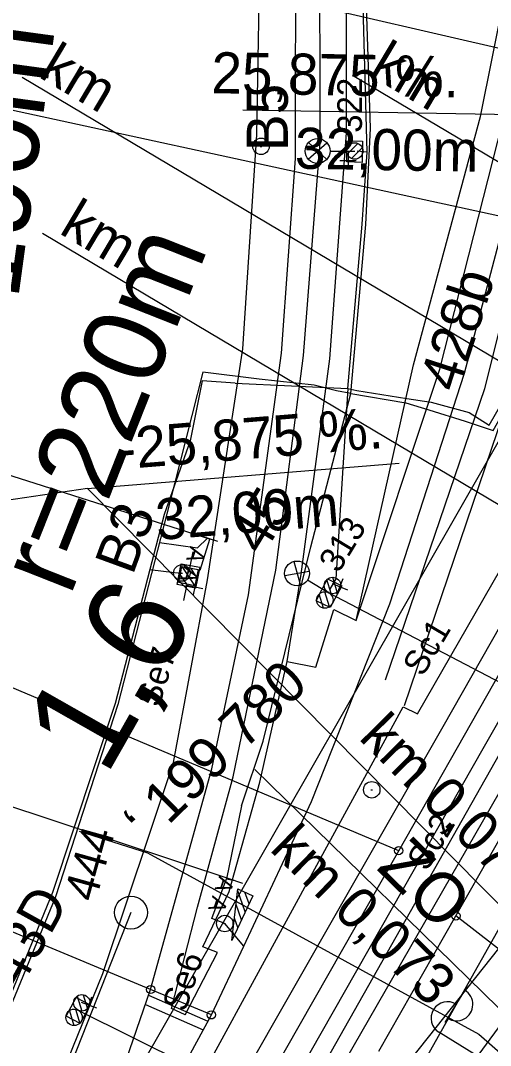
# Model space of a CAD drawing. Extents: x -598638 to -597933, y -1164002 to -1161904.
# Drawn here: x -598153.6 to -598125.1, y -1162835.6 to -1162773.3 of the extents above; entities that cross this region are included whole.
import ezdxf

# ---------------------------------------------------------------- set-up
doc = ezdxf.new("R2010")
doc.units = 0
for name, color, linetype in [('Vrstva 1', 7, 'Continuous'), ('Vrstva 11', 7, 'Continuous'), ('Vrstva 12', 7, 'Continuous'), ('Vrstva 25', 7, 'Continuous'), ('Vrstva 26', 7, 'Continuous'), ('Vrstva 28', 7, 'Continuous'), ('Vrstva 3', 7, 'Continuous'), ('Vrstva 4', 7, 'Continuous'), ('Vrstva 43', 7, 'Continuous'), ('Vrstva 44', 7, 'Continuous'), ('Vrstva 51', 7, 'Continuous'), ('Vrstva 6', 7, 'Continuous'), ('Vrstva 63', 7, 'Continuous'), ('Vrstva 7', 7, 'Continuous')]:
    doc.layers.add(name, color=color, linetype=linetype)

msp = doc.modelspace()

# ---------------------------------------------------------------- linework, layer by layer
at = {"layer": 'Vrstva 1'}
for p, q in [((-598179.707, -1162762.202), (-598122.033, -1162775.573)), ((-598121.14, -1162779.08), (-598140.138, -1162778.753)), ((-598130.653, -1162823.786), (-598208.738, -1162790.839)), ((-598149.562, -1162801.766), (-598130.625, -1162800.222)), ((-598149.562, -1162801.766), (-598168.362, -1162804.518)), ((-598116.195, -1162835.531), (-598149.562, -1162801.766)), ((-598139.409, -1162818.844), (-598119.244, -1162838.594)), ((-598069.482, -1162872.78), (-598127.174, -1162827.753))]:
    msp.add_line(p, q, dxfattribs=at)
for points in [[(-598185.535, -1162920.228), (-598173.482, -1162899.031), (-598147.832, -1162853.978), (-598130.653, -1162823.786), (-598124.876, -1162813.622), (-598094.683, -1162760.579), (-598072.513, -1162721.65)], [(-598148.903, -1162841.412), (-598145.736, -1162832.228), (-598142.003, -1162818.806), (-598139.787, -1162808.236), (-598137.783, -1162793.528), (-598136.933, -1162781.691), (-598136.909, -1162767.649), (-598137.878, -1162754.511), (-598139.595, -1162742.333), (-598141.999, -1162730.629), (-598144.153, -1162722.384)], [(-598131.857, -1162835.983), (-598127.174, -1162827.753), (-598120.322, -1162815.699), (-598090.855, -1162763.955), (-598078.437, -1162742.118)], [(-598124.171, -1162785.282), (-598204.376, -1162767.837), (-598201.647, -1162755.291), (-598220.808, -1162751.123)], [(-598146.747, -1162842.466), (-598142.041, -1162833.77), (-598140.075, -1162829.587), (-598135.947, -1162820.802), (-598131.192, -1162808.778), (-598126.663, -1162794.757), (-598124.171, -1162785.282), (-598123.05, -1162780.413), (-598122.033, -1162775.573)], [(-598142.041, -1162833.77), (-598145.736, -1162832.228), (-598280.672, -1162775.962)], [(-598148.348, -1162864.87), (-598137.826, -1162846.438), (-598130.316, -1162836.985), (-598124.577, -1162829.729), (-598115.364, -1162818.081), (-598094.508, -1162796.091)]]:
    msp.add_lwpolyline(points, dxfattribs=at)
for centre in [(-598130.653, -1162823.786), (-598127.174, -1162827.753), (-598145.735, -1162832.228), (-598142.041, -1162833.771)]:
    msp.add_circle(centre, 0.25, dxfattribs=at)
at = {"layer": 'Vrstva 11'}
for p, q in [((-598133.791, -1162781.424), (-598133.145, -1162780.778)), ((-598133.531, -1162781.694), (-598132.876, -1162781.039)), ((-598143.344, -1162806.609), (-598143.15, -1162805.618)), ((-598143.041, -1162807.654), (-598143.81, -1162806.507)), ((-598142.939, -1162807.134), (-598143.29, -1162806.61)), ((-598143.542, -1162807.579), (-598143.932, -1162806.999)), ((-598134.754, -1162808.15), (-598135.015, -1162807.294)), ((-598134.388, -1162808.065), (-598134.663, -1162807.16)), ((-598143.535, -1162807.577), (-598143.73, -1162808.562)), ((-598134.862, -1162808.949), (-598135.138, -1162808.042)), ((-598135.229, -1162809.033), (-598135.488, -1162808.179)), ((-598150.197, -1162832.63), (-598149.923, -1162833.538)), ((-598149.83, -1162832.548), (-598149.572, -1162833.402)), ((-598150.672, -1162833.515), (-598150.397, -1162834.419)), ((-598150.306, -1162833.43), (-598150.046, -1162834.286))]:
    msp.add_line(p, q, dxfattribs=at)
msp.add_lwpolyline([(-598144.027, -1162807.484), (-598143.834, -1162806.503), (-598142.853, -1162806.696), (-598143.046, -1162807.677)], close=True, dxfattribs=at)
for points in [[(-598144.027, -1162807.484), (-598143.834, -1162806.503), (-598142.853, -1162806.696), (-598143.046, -1162807.677), (-598144.027, -1162807.484)], [(-598134.91, -1162808.1), (-598112.16, -1162820)], [(-598150.15, -1162833.48), (-598130.19, -1162843.41)]]:
    msp.add_lwpolyline(points, dxfattribs=at)
for centre in [(-598133.33, -1162781.24), (-598134.675, -1162807.659), (-598134.675, -1162807.659), (-598135.145, -1162808.541), (-598135.145, -1162808.541), (-598149.914, -1162833.039), (-598149.914, -1162833.039), (-598150.386, -1162833.921), (-598150.386, -1162833.921)]:
    msp.add_circle(centre, 0.5, dxfattribs=at)
at = {"layer": 'Vrstva 12'}
for p, q in [((-598144.12, -1162807.6), (-598143.87, -1162806.34)), ((-598143.87, -1162806.34), (-598142.75, -1162806.55)), ((-598142.75, -1162806.55), (-598143, -1162807.82)), ((-598143, -1162807.82), (-598144.12, -1162807.6))]:
    msp.add_line(p, q, dxfattribs=at)
for points in [[(-598133.81, -1162781.9), (-598133.8, -1162780.62), (-598132.85, -1162780.63), (-598132.88, -1162781.94), (-598133.81, -1162781.9)], [(-598134.11, -1162807.67), (-598134.82, -1162809), (-598135.68, -1162808.6), (-598134.99, -1162807.25), (-598134.11, -1162807.67)], [(-598149.41, -1162833.16), (-598150.02, -1162834.3), (-598150.86, -1162833.84), (-598150.26, -1162832.71), (-598149.41, -1162833.16)]]:
    msp.add_lwpolyline(points, dxfattribs=at)
at = {"layer": 'Vrstva 25'}
for p, q in [((-598136.149, -1162781.736), (-598135.023, -1162780.734)), ((-598136.133, -1162780.721), (-598135.025, -1162781.744)), ((-598134.83, -1162781.24), (-598133.33, -1162781.24)), ((-598137.037, -1162806.202), (-598136.62, -1162807.651)), ((-598143.887, -1162806.902), (-598143.787, -1162806.902)), ((-598137.577, -1162807.061), (-598136.095, -1162806.789)), ((-598136.192, -1162807.322), (-598134.91, -1162808.1)), ((-598141.277, -1162828.216), (-598141.177, -1162828.216)), ((-598127.84, -1162834.231), (-598126.476, -1162832.017)), ((-598125.228, -1162836.663), (-598128.207, -1162834.827))]:
    msp.add_line(p, q, dxfattribs=at)
for centre, radius in [((-598135.584, -1162781.238), 0.754), ((-598136.833, -1162806.925), 0.754), ((-598143.837, -1162806.902), 0.5), ((-598141.227, -1162828.216), 0.5)]:
    msp.add_circle(centre, radius, dxfattribs=at)
for centre, start, end in [((-598127.148, -1162833.13), 237.65743, 59.06258), ((-598127.683, -1162833.975), 58.36001, 238.36001)]:
    msp.add_arc(centre, 1, start, end, dxfattribs=at)
at = {"layer": 'Vrstva 26'}
for points in [[(-598133.739, -1162795.688), (-598132.883, -1162785.694), (-598132.561, -1162781.304), (-598132.833, -1162771.673), (-598133.507, -1162753.613), (-598135.242, -1162744.453), (-598136.578, -1162735.815), (-598138.623, -1162726.488)], [(-598132.561, -1162781.304), (-598133.184, -1162781.255)], [(-598133.194, -1162795.797), (-598130.15, -1162796.289), (-598128.676, -1162796.517), (-598126.372, -1162797.148), (-598125.165, -1162797.901), (-598118.291, -1162785.968)], [(-598140.604, -1162795.346), (-598142.6, -1162795.212), (-598143.324, -1162798.859)], [(-598140.604, -1162795.346), (-598133.739, -1162795.688), (-598133.194, -1162795.797)], [(-598133.739, -1162795.688), (-598134.467, -1162807.255)], [(-598143.324, -1162798.859), (-598144.902, -1162803.35)], [(-598144.902, -1162803.35), (-598145.773, -1162806.692), (-598147.895, -1162814.835), (-598151.697, -1162826.333), (-598155.502, -1162835.602), (-598159.885, -1162844.8), (-598162.416, -1162850.038), (-598164.36, -1162853.511), (-598166.042, -1162857.118), (-598164.26, -1162864.862)], [(-598145.773, -1162806.692), (-598144.273, -1162806.868), (-598143.837, -1162806.902)], [(-598134.467, -1162807.255), (-598134.839, -1162807.891)], [(-598150.081, -1162822.602), (-598145.925, -1162823.915), (-598125.776, -1162834.952), (-598123.525, -1162836.909), (-598124.091, -1162837.542), (-598129.205, -1162843.998)]]:
    msp.add_lwpolyline(points, dxfattribs=at)
at = {"layer": 'Vrstva 28'}
msp.add_line((-598140.207, -1162821.051), (-598141.115, -1162825.493), dxfattribs=at)
for points in [[(-598133.568, -1162795.979), (-598132.654, -1162785.702), (-598132.374, -1162779.841), (-598132.629, -1162771.78), (-598133.203, -1162756.346), (-598133.291, -1162753.897), (-598135.063, -1162744.423), (-598136.348, -1162735.985), (-598138.696, -1162725.492), (-598140.441, -1162720.483), (-598146.202, -1162709.244), (-598149.531, -1162710.126), (-598150.562, -1162710.327), (-598151.192, -1162706.084), (-598153.437, -1162698.629), (-598154.996, -1162692.989), (-598155.846, -1162690.77), (-598154.797, -1162690.331), (-598151.984, -1162689.455), (-598149.559, -1162688.581), (-598149.218, -1162687.385), (-598151.36, -1162675.56), (-598154.253, -1162659.137), (-598152.294, -1162657.885)], [(-598133.568, -1162795.979), (-598130.221, -1162796.559), (-598128.822, -1162796.97), (-598126.618, -1162797.673), (-598124.922, -1162798.23), (-598117.755, -1162785.562)], [(-598140.207, -1162821.051), (-598138.9, -1162817.123), (-598135.993, -1162805.307), (-598133.568, -1162795.979), (-598134.442, -1162795.825), (-598135.794, -1162795.467), (-598139.137, -1162795.121), (-598142.554, -1162794.689), (-598144.563, -1162802.596), (-598147.734, -1162814.888), (-598151.511, -1162826.59), (-598155.288, -1162835.731), (-598159.67, -1162844.896), (-598162.194, -1162850.186), (-598164.133, -1162853.664), (-598165.736, -1162857.055), (-598164.017, -1162864.873)], [(-598145.197, -1162805.054), (-598142.887, -1162805.379), (-598142.27, -1162804.791)], [(-598140.075, -1162829.587), (-598141.227, -1162828.216), (-598142.007, -1162827.909), (-598141.115, -1162825.493)], [(-598141.115, -1162825.493), (-598140.617, -1162825.598)]]:
    msp.add_lwpolyline(points, dxfattribs=at)
at = {"layer": 'Vrstva 3'}
for p, q in [((-598139.979, -1162827.501), (-598140.441, -1162826.218)), ((-598139.753, -1162827.021), (-598140.012, -1162826.301)), ((-598139.528, -1162826.542), (-598139.533, -1162826.527)), ((-598140.204, -1162827.981), (-598140.54, -1162827.052)), ((-598140.43, -1162828.461), (-598140.638, -1162827.884)), ((-598140.656, -1162828.942), (-598140.736, -1162828.716))]:
    msp.add_line(p, q, dxfattribs=at)
msp.add_lwpolyline([(-598140.799, -1162829.247), (-598140.429, -1162826.107), (-598139.524, -1162826.531), (-598140.799, -1162829.247)], dxfattribs=at)
msp.add_lwpolyline([(-598140.799, -1162829.247), (-598140.429, -1162826.107), (-598139.524, -1162826.531), (-598140.799, -1162829.247)], dxfattribs=at)
at = {"layer": 'Vrstva 4'}
for points in [[(-598189.853, -1162912.957), (-598181.357, -1162896.669), (-598172.758, -1162881.845), (-598166.709, -1162871.526), (-598158.957, -1162856.49), (-598153.453, -1162843.163), (-598148.638, -1162831.263), (-598144.347, -1162818.421), (-598142.283, -1162807.307), (-598140.136, -1162793.268), (-598139.285, -1162780.248), (-598139.053, -1162767.58), (-598140.211, -1162754.845), (-598141.396, -1162743.83), (-598143.05, -1162731.285)], [(-598136.668, -1162850.995), (-598119.65, -1162827.832), (-598111.306, -1162818.425), (-598097.627, -1162804.2), (-598093.831, -1162800.263), (-598081.499, -1162787.848), (-598070.515, -1162776.315), (-598054.627, -1162758.515)], [(-598137.443, -1162812.291), (-598135.696, -1162812.632), (-598134.599, -1162809.128)]]:
    msp.add_lwpolyline(points, dxfattribs=at)
at = {"layer": 'Vrstva 43'}
msp.add_circle((-598146.929, -1162827.551), 1, dxfattribs=at)
at = {"layer": 'Vrstva 44'}
for points in [[(-598295.758, -1163493.483), (-598278.118, -1163452.874), (-598264.209, -1163410.565), (-598254.468, -1163367.19), (-598248.62, -1163321.577), (-598253.497, -1163320.887), (-598249.615, -1163272.581), (-598247.635, -1163222.481), (-598247.486, -1163176.779), (-598247.442, -1163130.148), (-598244.014, -1163084.171), (-598235.33, -1163037.762), (-598224.817, -1163002.559), (-598219.379, -1163002.169), (-598206.652, -1162968.487), (-598191.401, -1162936.053), (-598173.754, -1162904.506), (-598155.689, -1162873.083), (-598136.14, -1162838.446), (-598116.776, -1162804.197)], [(-598214.433, -1163003.397), (-598199.219, -1162964.022), (-598185.65, -1162936.04), (-598163.291, -1162895.981), (-598150.219, -1162876.092), (-598140.441, -1162856.726), (-598110.998, -1162804.439)], [(-598146.929, -1162827.551), (-598158.836, -1162857.646), (-598178.917, -1162893.572)]]:
    msp.add_lwpolyline(points, dxfattribs=at)
at = {"layer": 'Vrstva 51'}
for points in [[(-598178.434, -1162902.74), (-598173.075, -1162891.876), (-598150.908, -1162852.698), (-598130.373, -1162815.033), (-598129.52, -1162815.457), (-598097.649, -1162759.965), (-598075.416, -1162720.73), (-598062.421, -1162699.093), (-598047.075, -1162676.157), (-598029.931, -1162650.253)], [(-598178.434, -1162902.74), (-598177.624, -1162903.197), (-598171.581, -1162892.624), (-598149.282, -1162853.595), (-598127.952, -1162816.235), (-598096.388, -1162760.674), (-598074.046, -1162721.426), (-598061.02, -1162699.878), (-598045.71, -1162676.963), (-598028.725, -1162651.098), (-598029.931, -1162650.253)], [(-598243.76, -1163139.382), (-598243.393, -1163128.836), (-598242.662, -1163113.52), (-598241.121, -1163096.732), (-598238.542, -1163077.297), (-598236.364, -1163063.881), (-598233.006, -1163047.35), (-598229.452, -1163032.186), (-598222.566, -1163008.635), (-598216.788, -1162991.447), (-598211.314, -1162977.141), (-598198.954, -1162949.031), (-598191.954, -1162935.136), (-598181.215, -1162915.654), (-598172.367, -1162900.092), (-598146.639, -1162854.694), (-598125.435, -1162817.431), (-598123.403, -1162813.873), (-598093.874, -1162762.323), (-598071.494, -1162722.83), (-598058.726, -1162701.732), (-598043.403, -1162678.606), (-598026.165, -1162652.845)], [(-598239.095, -1163097.092), (-598236.576, -1163077.501), (-598234.309, -1163064.254), (-598231.064, -1163047.867), (-598227.331, -1163032.522), (-598220.677, -1163009.309), (-598214.847, -1162992.197), (-598209.449, -1162977.846), (-598197.189, -1162949.981), (-598190.09, -1162935.876), (-598179.544, -1162916.618), (-598170.666, -1162900.915), (-598144.793, -1162855.5), (-598123.538, -1162818.503), (-598121.573, -1162814.996), (-598092.208, -1162763.361), (-598069.503, -1162724.253), (-598055.71, -1162703.114), (-598040.468, -1162680.627), (-598023.352, -1162655.056), (-598026.165, -1162652.845)], [(-598143.639, -1162833.769), (-598144.474, -1162833.39), (-598142.887, -1162827.226), (-598140.722, -1162819.3), (-598138.124, -1162806.733), (-598136.451, -1162793.663), (-598135.418, -1162780.713), (-598135.449, -1162767.439), (-598136.413, -1162754.506), (-598138.125, -1162741.945), (-598140.581, -1162730.014)], [(-598143.639, -1162833.769), (-598141.66, -1162829.974), (-598142.55, -1162829.627), (-598140.952, -1162826.266), (-598139.089, -1162819.621), (-598137.443, -1162812.291), (-598136.577, -1162806.979), (-598134.84, -1162793.881), (-598133.819, -1162780.129), (-598133.832, -1162767.002), (-598134.817, -1162754.969), (-598136.682, -1162741.592), (-598139.151, -1162729.736), (-598140.581, -1162730.014)], [(-598131.459, -1162813.387), (-598125.418, -1162795.68), (-598121.535, -1162780.187), (-598118.021, -1162762.938), (-598116.444, -1162763.202)], [(-598130.3, -1162814.964), (-598123.885, -1162796.017), (-598119.967, -1162780.726), (-598116.444, -1162763.202)], [(-598134.599, -1162809.128), (-598133.246, -1162809.796), (-598129.747, -1162794.246), (-598125.683, -1162779.142), (-598123.45, -1162768.029), (-598121.981, -1162768.211)], [(-598133.246, -1162809.796), (-598128.158, -1162794.502), (-598124.333, -1162779.452), (-598121.981, -1162768.211)]]:
    msp.add_lwpolyline(points, dxfattribs=at)
at = {"layer": 'Vrstva 6'}
for p, q in [((-598119.176, -1162797.214), (-598153.55, -1162776.76)), ((-598099.098, -1162797.092), (-598133.472, -1162776.638)), ((-598117.928, -1162806.716), (-598152.302, -1162786.262)), ((-598142.127, -1162804.836), (-598180.238, -1162792.692)), ((-598142.729, -1162806.724), (-598142.127, -1162804.838)), ((-598141.651, -1162804.99), (-598142.603, -1162804.686)), ((-598178.588, -1162813.02), (-598140.617, -1162825.598)), ((-598141.092, -1162825.441), (-598140.142, -1162825.755))]:
    msp.add_line(p, q, dxfattribs=at)
at = {"layer": 'Vrstva 63'}
msp.add_line((-598215.837, -1162958.494), (-598115.28, -1162782.61), dxfattribs=at)
at = {"layer": 'Vrstva 7'}
for p, q in [((-598139.073, -1162780.956), (-598138.973, -1162780.956)), ((-598133.736, -1162781.313), (-598133.736, -1162782.313)), ((-598134.236, -1162781.813), (-598133.236, -1162781.813)), ((-598142.942, -1162807.248), (-598143.146, -1162808.226)), ((-598134.693, -1162807.537), (-598133.767, -1162807.915)), ((-598134.041, -1162807.263), (-598134.419, -1162808.189)), ((-598143.533, -1162807.635), (-598142.555, -1162807.839)), ((-598132.341, -1162820.084), (-598132.241, -1162820.084)), ((-598149.961, -1162833.005), (-598149.017, -1162833.337)), ((-598149.323, -1162832.699), (-598149.655, -1162833.643)), ((-598145.856, -1162832.576), (-598142.252, -1162834.16)), ((-598146.052, -1162833.146), (-598142.539, -1162834.69))]:
    msp.add_line(p, q, dxfattribs=at)
for centre in [(-598139.023, -1162780.956), (-598132.291, -1162820.084)]:
    msp.add_circle(centre, 0.5, dxfattribs=at)

# ---------------------------------------------------------------- texts
at = {"layer": 'Vrstva 1'}
for s, height, rotation, p in [('r=190m', 5, 82.24109, (-598154.628, -1162796.434)), ('25,875 %.', 2.5, 359.01583, (-598142.057, -1162777.72)), ('32,00m', 2.5, 359.01583, (-598136.976, -1162782.308)), ('r=220m', 5, 68.42323, (-598150.634, -1162808.384)), ('428b', 2.5, 72.09874, (-598127.063, -1162795.995)), ('-25,875 %.', 2.5, 4.66008, (-598147.65, -1162800.606)), ('32,00m', 2.5, 4.66008, (-598145.326, -1162804.905)), ('‘ 199 780  ', 2.5, 44.66008, (-598145.846, -1162823.448)), ('km 0,077', 2.5, 314.66008, (-598133.137, -1162816.964)), ('km 0,073', 2.5, 315.62032, (-598138.558, -1162823.749)), ('ZO', 3, 315.59565, (-598132.066, -1162824.878))]:
    msp.add_text(s, height=height, rotation=rotation, dxfattribs=at).set_placement(p)
at = {"layer": 'Vrstva 11'}
for s, rotation, p in [('B5', 90, (-598137.393, -1162781.24)), ('45', 58.7004, (-598138.923, -1162805.913)), ('B3', 69.86031, (-598146.826, -1162807.09)), ('43D', 60.97988, (-598153.649, -1162832.238))]:
    msp.add_text(s, height=2.5, rotation=rotation, dxfattribs=at).set_placement(p)
at = {"layer": 'Vrstva 25'}
for s, rotation, p in [('322', 90, (-598132.887, -1162780.131)), ('313', 58.74239, (-598134.314, -1162806.963))]:
    msp.add_text(s, height=1.5, rotation=rotation, dxfattribs=at).set_placement(p)
at = {"layer": 'Vrstva 43'}
msp.add_text('444', height=2, rotation=74.4574, dxfattribs=at).set_placement((-598149.09, -1162826.974))
at = {"layer": 'Vrstva 6'}
for s, height, rotation, p in [('km ', 2.5, 329.24371, (-598132.538, -1162776.581)), ('km ', 2.5, 329.24371, (-598152.616, -1162776.703)), ('km ', 2.5, 329.24371, (-598151.368, -1162786.205)), ('  A A', 1, 252.32535, (-598143.08, -1162804.532)), ('Sc1', 1.5, 59.24371, (-598129.203, -1162813.265)), ('Se7', 1.5, 72.32535, (-598145.235, -1162815.124)), ('Sc2', 1.5, 59.24371, (-598128.942, -1162825.1)), ('A A', 1, 251.6731, (-598141.566, -1162825.284)), ('Se6', 1.5, 71.6731, (-598143.627, -1162833.647))]:
    msp.add_text(s, height=height, rotation=rotation, dxfattribs=at).set_placement(p)
at = {"layer": 'Vrstva 7'}
msp.add_text('1,6', height=6, rotation=60.38703, dxfattribs=at).set_placement((-598148.457, -1162819.343))

doc.saveas('drawing.dxf')
